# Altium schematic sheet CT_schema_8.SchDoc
size 278 x 170 mm
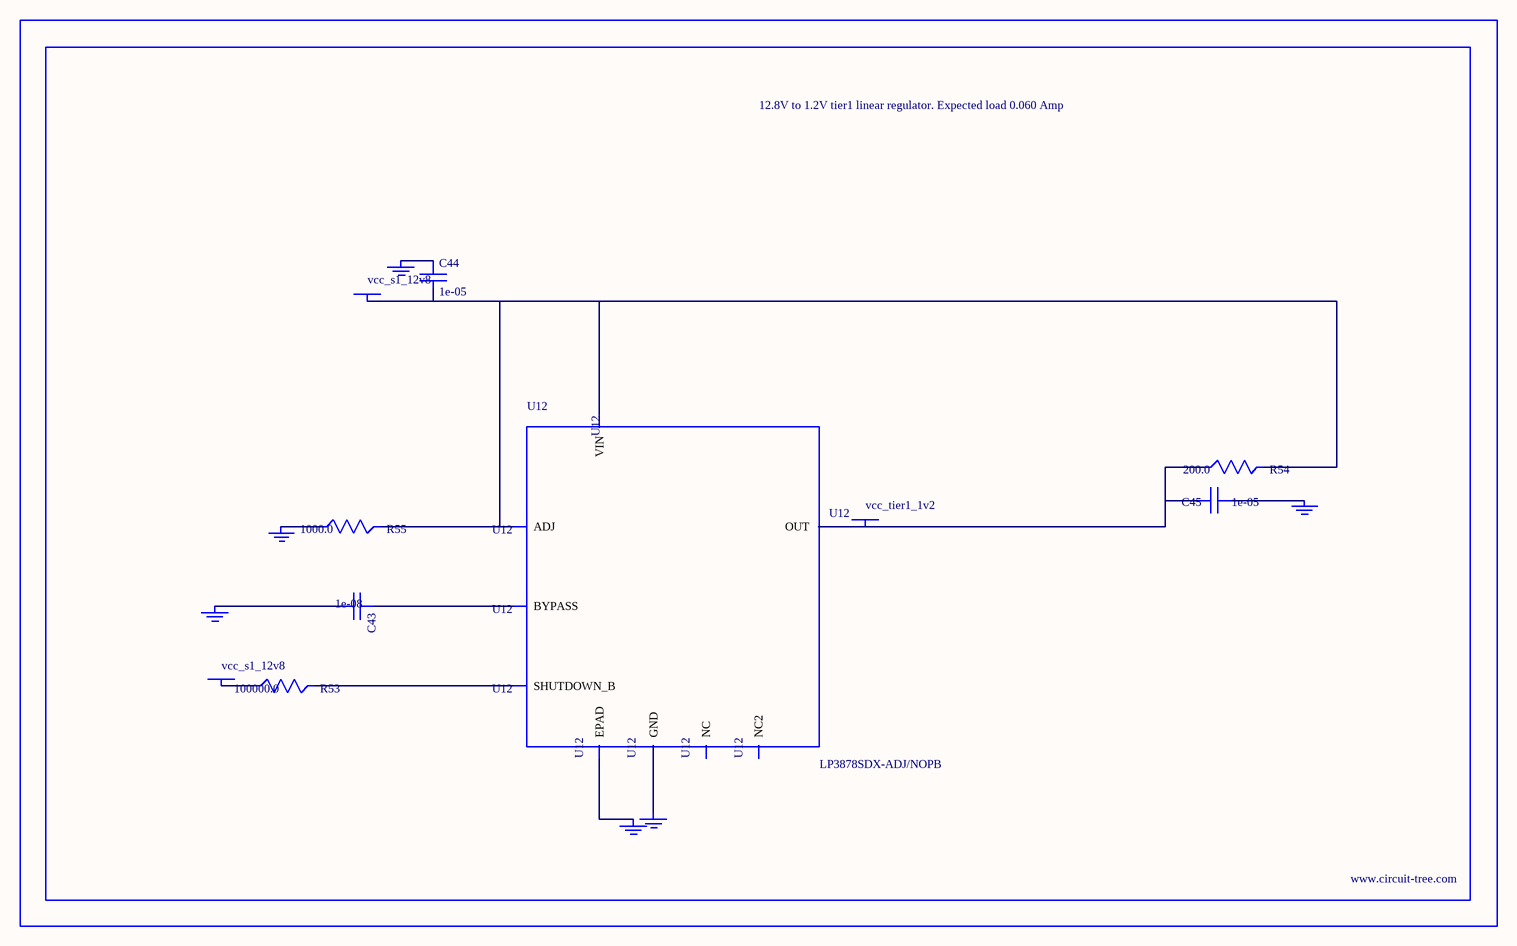
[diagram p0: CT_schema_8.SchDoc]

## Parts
BORDER7  (no value)
C43  1e-08  [C0402]
C44  1e-05  [C1210]
C45  1e-05  [C0805]
GND_INSTANCE_7_0  (no value)
GND_INSTANCE_7_1  (no value)
GND_INSTANCE_7_2  (no value)
GND_INSTANCE_7_3  (no value)
GND_INSTANCE_7_4  (no value)
GND_INSTANCE_7_5  (no value)
POWER_INSTANCE_7_0  vcc_s1_12v8
POWER_INSTANCE_7_1  vcc_s1_12v8
POWER_INSTANCE_7_2  vcc_tier1_1v2
R53  100000.0  [R0603]
R54  200.0  [R0603]
R55  1000.0  [R0603]
U12  LP3878SDX-ADJ/NOPB  [WSON-8]

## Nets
NetC43_1: C43.1 U12.1(BYPASS)
NetC43_2: C43.2 GND_INSTANCE_7_0.0(GND)
NetC44_1: C44.1 GND_INSTANCE_7_1.0(GND)
NetC44_2: C44.2 POWER_INSTANCE_7_0.0(PWR) R54.2 R55.2 U12.4(VIN) U12.6(ADJ)
NetC45_1: C45.1 GND_INSTANCE_7_2.0(GND)
NetC45_2: C45.2 POWER_INSTANCE_7_2.0(PWR) R54.1 U12.5(OUT)
NetGND_INSTANCE_7_3_0: GND_INSTANCE_7_3.0(GND) R55.1
NetGND_INSTANCE_7_4_0: GND_INSTANCE_7_4.0(GND) U12.PAD(EPAD)
NetGND_INSTANCE_7_5_0: GND_INSTANCE_7_5.0(GND) U12.3(GND)
NetPOWER_INSTANCE_7_1_0: POWER_INSTANCE_7_1.0(PWR) R53.1
NetR53_2: R53.2 U12.8(SHUTDOWN_B)

Not connected (* = marked no-connect by the designer): U12 2(NC) 7(NC2)

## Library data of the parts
BORDER7 = BORDER_PAGE7
C43 = C0402C103K3RAC
C44 = C1210C106K5PACTU
C45 = GRM219R60J106ME19D
GND_INSTANCE_7_0-GND_INSTANCE_7_5 = GND
POWER_INSTANCE_7_0-POWER_INSTANCE_7_2 = PWR
R53 = RC0603JR-07100KL
R54 = RC0603JR-07200RL
R55 = RC0603JR-071KL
